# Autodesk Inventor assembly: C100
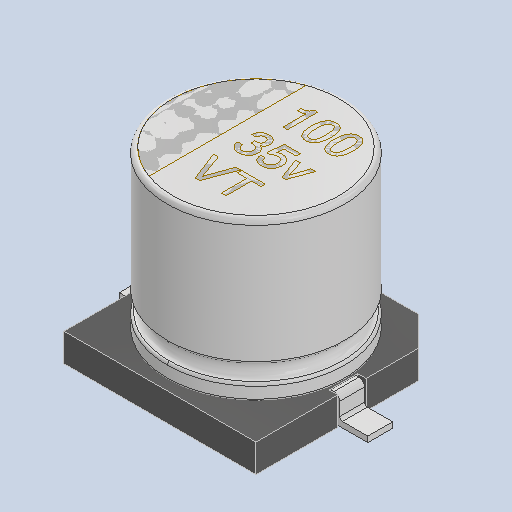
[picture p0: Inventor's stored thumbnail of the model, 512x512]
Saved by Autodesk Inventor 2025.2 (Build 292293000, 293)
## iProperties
Created: 2025-04
Part Number: C100
Description: PART--DESC
Document SubType Name: Assembly
Designer: BennF
Author: BennF
Revision Number: NONE
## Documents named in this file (4)
- C:\Users\BennF\Nextcloud\Benutzer\CNC JarBeRi\existing parts\Electronics\RepRap A4988 Shied (USE WITHOUT ARDUINO)\reprap-a4988-1.snapshot.1\RepRap\RepRap\C100_5.iam
- C:\Users\BennF\Nextcloud\Benutzer\CNC JarBeRi\existing parts\Electronics\RepRap A4988 Shied (USE WITHOUT ARDUINO)\reprap-a4988-1.snapshot.1\RepRap\RepRap\C100 Geometry.ipt
- C:\Users\BennF\Nextcloud\Benutzer\CNC JarBeRi\existing parts\Electronics\RepRap A4988 Shied (USE WITHOUT ARDUINO)\reprap-a4988-1.snapshot.1\RepRap\RepRap\name3.ipt
- C:\Users\BennF\Nextcloud\Benutzer\CNC JarBeRi\existing parts\Electronics\RepRap A4988 Shied (USE WITHOUT ARDUINO)\reprap-a4988-1.snapshot.1\RepRap\RepRap\bay_5.iam
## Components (3 placed, 3 different names)
1. C100 Geometry
2. name3
3. bay [sub-assembly]
